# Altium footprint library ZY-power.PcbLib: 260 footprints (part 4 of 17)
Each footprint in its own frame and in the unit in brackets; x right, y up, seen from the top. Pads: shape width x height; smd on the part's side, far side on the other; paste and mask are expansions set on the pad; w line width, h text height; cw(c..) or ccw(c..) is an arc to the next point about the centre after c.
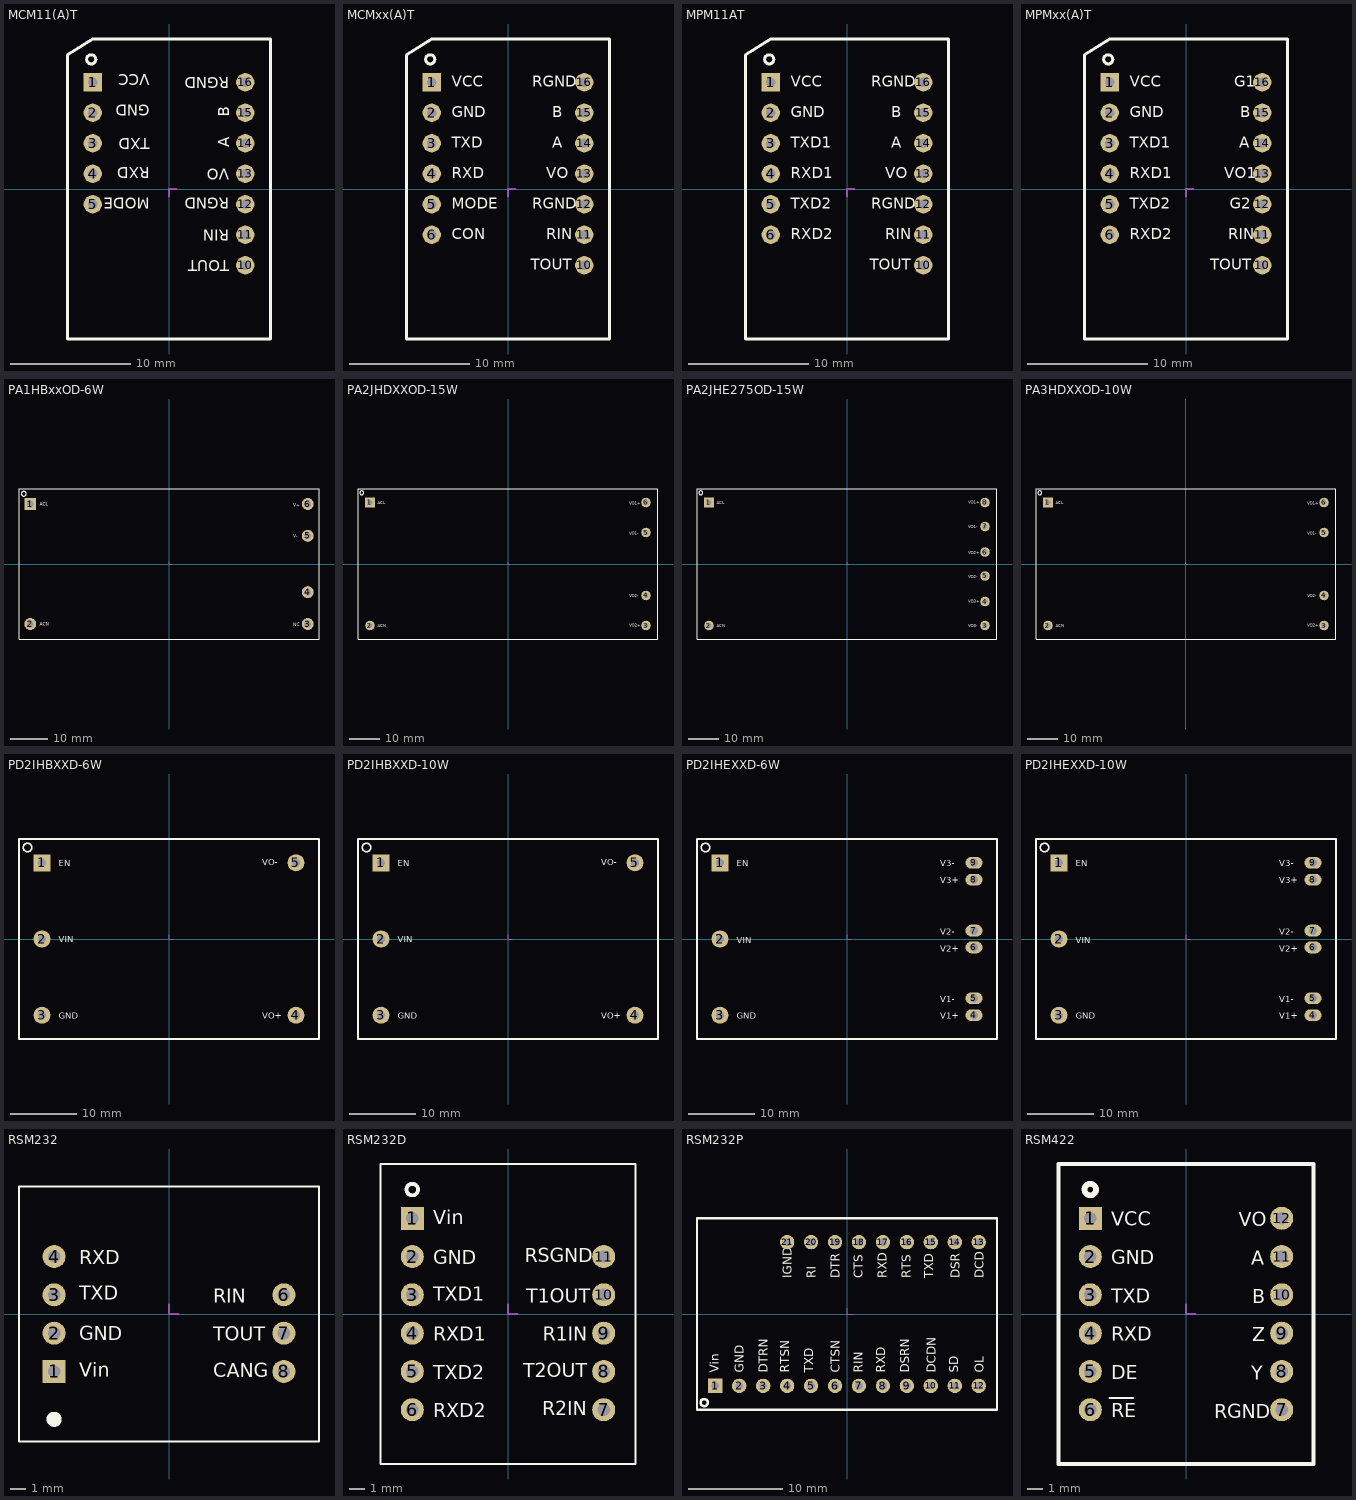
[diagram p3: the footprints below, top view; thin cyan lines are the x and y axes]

## MCM11(A)T [mil]
height 279.53
pads (12):
  rect 60x60 hole 32: 1(-250,350)
  round 60 hole 32: 2(-250,250) 3(-250,150) 4(-250,50) 5(-250,-50) 10(250,-250) 11(250,-150) 12(250,-50) 13(250,50) 14(250,150) 15(250,250) 16(250,350)
Top Overlay:
  circle w10: c-255,425 r15
  lines w10: -249.97,491.68 -332.68,440 -332.68,-491.73 332.68,-491.73 332.68,491.73 -249.97,491.73
  text "RGND" at 197.68,366.73 h36
  text "B" at 197.68,236.73 h36
  text "A" at 197.68,136.73 h36
  text "VO" at 197.68,66.73 h36
  text "RGND" at 197.68,-28.27 h36
  text "RIN" at 197.68,-133.27 h36
  text "TOUT" at 197.68,-233.27 h36
  text "MODE" at -62.32,-28.27 h36
  text "RXD" at -62.32,71.73 h36
  text "TXD" at -62.32,166.73 h36
  text "GND" at -62.32,276.73 h36
  text "VCC" at -62.32,376.73 h36
Mechanical 15:
  lines w5: 0,-25 0,0 25,0

## MCMxx(A)T [mil]
height 279.53
pads (13):
  rect 60x60 hole 32: 1(-250,350)
  round 60 hole 32: 2(-250,250) 3(-250,150) 4(-250,50) 5(-250,-50) 6(-250,-150) 10(250,-250) 11(250,-150) 12(250,-50) 13(250,50) 14(250,150) 15(250,250) 16(250,350)
Top Overlay:
  circle w10: c-255,425 r15
  lines w10: -249.97,491.68 -332.68,440 -332.68,-491.73 332.68,-491.73 332.68,491.73 -249.97,491.73
  text "MODE" at -185,-65 h36
  text "CON" at -185,-165 h36
  text "RGND" at 80,335 h36
  text "B" at 145,235 h36
  text "A" at 145,135 h36
  text "VO" at 125,35 h36
  text "RGND" at 80,-65 h36
  text "RIN" at 125,-165 h36
  text "TOUT" at 75,-265 h36
  text "RXD" at -185,35 h36
  text "TXD" at -185,135 h36
  text "GND" at -185,235 h36
  text "VCC" at -185,335 h36
Mechanical 15:
  lines w5: 0,-25 0,0 25,0

## MPM11AT [mil]
height 279.53
pads (13):
  rect 60x60 hole 32: 1(-250,350)
  round 60 hole 32: 2(-250,250) 3(-250,150) 4(-250,50) 5(-250,-50) 6(-250,-150) 10(250,-250) 11(250,-150) 12(250,-50) 13(250,50) 14(250,150) 15(250,250) 16(250,350)
Top Overlay:
  circle w10: c-255,425 r15
  lines w10: -249.97,491.68 -332.68,440 -332.68,-491.73 332.68,-491.73 332.68,491.73 -249.97,491.73
  text "TXD2" at -185,-65 h36
  text "RXD2" at -185,-165 h36
  text "RGND" at 80,335 h36
  text "B" at 145,235 h36
  text "A" at 145,135 h36
  text "VO" at 125,35 h36
  text "RGND" at 80,-65 h36
  text "RIN" at 125,-165 h36
  text "TOUT" at 75,-265 h36
  text "RXD1" at -185,35 h36
  text "TXD1" at -185,135 h36
  text "GND" at -185,235 h36
  text "VCC" at -185,335 h36
Mechanical 15:
  lines w5: 0,-25 0,0 25,0

## MPMxx(A)T [mil]
height 279.53
pads (13):
  rect 60x60 hole 32: 1(-250,350)
  round 60 hole 32: 2(-250,250) 3(-250,150) 4(-250,50) 5(-250,-50) 6(-250,-150) 10(250,-250) 11(250,-150) 12(250,-50) 13(250,50) 14(250,150) 15(250,250) 16(250,350)
Top Overlay:
  circle w10: c-255,425 r15
  lines w10: -249.97,491.68 -332.68,440 -332.68,-491.73 332.68,-491.73 332.68,491.73 -249.97,491.73
  text "TXD2" at -185,-65 h36
  text "RXD2" at -185,-165 h36
  text "G1" at 158.94,335 h36
  text "B" at 177.45,235 h36
  text "A" at 174.02,135 h36
  text "VO1" at 125,35 h36
  text "G2" at 143.51,-65 h36
  text "RIN" at 137.85,-165 h36
  text "TOUT" at 79.41,-265 h36
  text "RXD1" at -185,35 h36
  text "TXD1" at -185,135 h36
  text "GND" at -185,235 h36
  text "VCC" at -185,335 h36
Mechanical 15:
  lines w5: 0,-25 0,0 25,0

## PA1HBxxOD-6W [mm]
pads (6):
  rect 3.175x3.175 hole 1.778: 1(-37,16)
  round 3.175 hole 1.778: 2(-37,-16) 3(37,-16) 4(37,-7.5) 5(37,7.5) 6(37,16)
Top Overlay:
  circle w0.254: c-38.73,18.73 r0.635
  lines w0.254: -40,-20 -40,20 40,20 40,-20 -40,-20
  text "NC" at 33.19,-16.635 h0.91
  text "V-" at 33.19,6.987 h0.91
  text "V+" at 33.19,15.24 h0.91
  text "ACN" at -34.46,-16.506 h0.91
  text "ACL" at -34.46,15.494 h0.91
Mechanical 15:
  lines w0.127: 0,0.635 0,0 0.635,0

## PA2JHDXXOD-15W [mm]
pads (6):
  rect 3.175x3.175 hole 1.778: 1(-46,20.5)
  round 3.175 hole 1.778: 2(-46,-20.5) 3(46,-20.5) 4(46,-10.5) 5(46,10.5) 6(46,20.5)
Top Overlay:
  circle w0.254: c-48.73,23.73 r0.635
  lines w0.254: -50,-25 50,-25 50,25 -50,25 -50,-25
  text "ACL" at -43.46,19.939 h0.91
  text "ACN" at -43.46,-21.061 h0.91
  text "VO2+" at 40.412,-20.955 h0.91
  text "VO2-" at 40.412,-11.049 h0.91
  text "VO1-" at 40.412,9.779 h0.91
  text "VO1+" at 40.412,19.779 h0.91
Mechanical 15:
  lines w0.127: 0,0.635 0,0 0.635,0

## PA2JHE275OD-15W [mm]
pads (8):
  rect 3.175x3.175 hole 1.778: 1(-46,20.5)
  round 3.175 hole 1.778: 2(-46,-20.5) 3(46,-20.5) 4(46,-12.5) 5(46,-4) 6(46,4) 7(46,12.5) 8(46,20.5)
Top Overlay:
  circle w0.254: c-48.73,23.73 r0.635
  lines w0.254: -50,-25 50,-25 50,25 -50,25 -50,-25
  text "ACL" at -43.46,19.939 h0.91
  text "ACN" at -43.46,-21.061 h0.91
  text "VO3+" at 40.412,-12.954 h0.91
  text "VO3-" at 40.412,-21.082 h0.91
  text "VO1-" at 40.412,11.938 h0.91
  text "VO1+" at 40.412,20.033 h0.91
  text "VO2+" at 40.412,3.302 h0.91
  text "VO2-" at 40.412,-4.699 h0.91
Mechanical 15:
  lines w0.127: 0,0.635 0,0 0.635,0

## PA3HDXXOD-10W [mm]
pads (6):
  rect 3.175x3.175 hole 1.778: 1(-46,20.5)
  round 3.175 hole 1.778: 2(-46,-20.5) 3(46,-20.5) 4(46,-10.5) 5(46,10.5) 6(46,20.5)
Top Overlay:
  circle w0.254: c-48.73,23.73 r0.635
  lines w0.254: -50,-25 -50,25 50,25 50,-25 -50,-25
  text "VO1+" at 40.412,19.779 h0.91
  text "VO1-" at 40.412,9.779 h0.91
  text "VO2-" at 40.412,-11.049 h0.91
  text "VO2+" at 40.412,-20.955 h0.91
  text "ACN" at -43.46,-21.061 h0.91
  text "ACL" at -43.46,19.939 h0.91
Mechanical 15:
  lines w0.127: 0,0.635 0,0 0.635,0

## PD2IHBXXD-6W [mil]
pads (5):
  rect 100x100 hole 50: 1(-750,450)
  round 100 hole 50: 2(-750,0) 3(-750,-450) 4(750,-450) 5(750,450)
Top Overlay:
  circle w10: c-835.83,540.55 r25
  lines w10: -885.83,-590.55 -885.83,590.55 885.83,590.55 885.83,-590.55 -885.83,-590.55
  text "EN" at -650,430.08 h36
  text "VIN" at -650,-19.92 h36
  text "GND" at -650,-469.92 h36
  text "VO+" at 550,-470 h36
  text "VO-" at 550,435 h36
Mechanical 15:
  lines w5: 0,25 0,0 25,0

## PD2IHBXXD-10W [mil]
pads (5):
  rect 100x100 hole 50: 1(-750,450)
  round 100 hole 50: 2(-750,0) 3(-750,-450) 4(750,-450) 5(750,450)
Top Overlay:
  circle w10: c-835.83,540.55 r25
  lines w10: -885.83,-590.55 885.83,-590.55 885.83,590.55 -885.83,590.55 -885.83,-590.55
  text "VO-" at 550,435 h36
  text "VO+" at 550,-470 h36
  text "GND" at -650,-469.92 h36
  text "VIN" at -650,-19.92 h36
  text "EN" at -650,430.08 h36
Mechanical 15:
  lines w5: 0,25 0,0 25,0

## PD2IHEXXD-6W [mil]
pads (9):
  rect 100x100 hole 50 unplated: 1(-750,450)
  round 100 hole 50 unplated: 2(-750,0) 3(-750,-450)
  oval 100x70 hole 50 unplated: 4(750,-450) 5(750,-350) 6(750,-50) 7(750,50) 8(750,350) 9(750,450)
Top Overlay:
  circle w10: c-835.83,540.55 r25
  lines w10: -885.83,-590.55 885.83,-590.55 885.83,590.55 -885.83,590.55 -885.83,-590.55
  text "EN" at -650,430 h36
  text "VIN" at -650,-25 h36
  text "GND" at -650,-470 h36
  text "V1+" at 550,-470 h36
  text "V1-" at 550,-375 h36
  text "V2+" at 550,-75 h36
  text "V2-" at 550,25 h36
  text "V3+" at 550,330 h36
  text "V3-" at 550,430 h36
Mechanical 15:
  lines w5: 0,25 0,0 25,0

## PD2IHEXXD-10W [mil]
pads (9):
  rect 100x100 hole 50 unplated: 1(-750,450)
  round 100 hole 50 unplated: 2(-750,0) 3(-750,-450)
  oval 100x70 hole 50 unplated: 4(750,-450) 5(750,-350) 6(750,-50) 7(750,50) 8(750,350) 9(750,450)
Top Overlay:
  circle w10: c-835.83,540.55 r25
  lines w10: -885.83,-590.55 885.83,-590.55 885.83,590.55 -885.83,590.55 -885.83,-590.55
  text "EN" at -650,430 h36
  text "VIN" at -650,-25 h36
  text "GND" at -650,-470 h36
  text "V1+" at 550,-470 h36
  text "V1-" at 550,-375 h36
  text "V2+" at 550,-75 h36
  text "V2-" at 550,25 h36
  text "V3+" at 550,330 h36
  text "V3-" at 550,430 h36
Mechanical 15:
  lines w5: 0,25 0,0 25,0

## RSM232 [mil]
height 279.53
pads (7):
  rect 60x60 hole 32: 1(-300,-150)
  round 60 hole 32: 2(-300,-50) 3(-300,50) 4(-300,150) 6(300,50) 7(300,-50) 8(300,-150)
Top Overlay:
  circle w19.68: c-300,-275 r9.84
  lines w5: -391.73,-332.68 391.73,-332.68 391.73,332.68 -391.73,332.68 -391.73,-332.68
  text "RIN" at 115,30 h36
  text "TOUT" at 115,-70 h36
  text "Vin" at -235,-164 h36
  text "GND" at -235,-69 h36
  text "TXD" at -235,37 h36
  text "RXD" at -235,130 h36
  text "CANG" at 115,-165 h36
Mechanical 15:
  lines w5: 0,25 0,0 25,0

## RSM232D [mil]
height 279.53
pads (11):
  rect 60x60 hole 32: 1(-250,250)
  round 60 hole 32: 2(-250,150) 3(-250,50) 4(-250,-50) 5(-250,-150) 6(-250,-250) 7(250,-250) 8(250,-150) 9(250,-50) 10(250,50) 11(250,150)
Top Overlay:
  circle w10: c-250,325 r15
  lines w5: -332.68,-391.73 332.68,-391.73 332.68,391.73 -332.68,391.73 -332.68,-391.73
  text "RXD2" at -195,-270 h36
  text "TXD2" at -195,-170 h36
  text "R2IN" at 89.37,-265 h36
  text "T2OUT" at 40.16,-165 h36
  text "R1IN" at 91.34,-70 h36
  text "RXD1" at -195,-70 h36
  text "TXD1" at -195,35 h36
  text "GND" at -195,130 h36
  text "Vin" at -195,235 h36
  text "T1OUT" at 48.03,30 h36
  text "RSGND" at 44.09,135 h36
Mechanical 15:
  lines w5: 0,25 0,0 25,0

## RSM232P [mil]
height 413.39
pads (21):
  rect 60x60 hole 32: 1(-550,-300)
  round 60 hole 32: 2(-450,-300) 3(-350,-300) 4(-250,-300) 5(-150,-300) 6(-50,-300) 7(50,-300) 8(150,-300) 9(250,-300) 10(350,-300) 11(450,-300) 12(550,-300) 13(550,300) 14(450,300) 15(350,300) 16(250,300) 17(150,300) 18(50,300) 19(-50,300) 20(-150,300) 21(-250,300)
Top Overlay:
  circle w10: c-595.98,-369.61 r15
  lines w10: -625.98,-399.61 625.98,-399.61 625.98,399.61 -625.98,399.61 -625.98,-399.61
  text "Vin" at -535,-245 h36
  text "GND" at -430,-245 h36
  text "DTRN" at -330,-245 h36
  text "RTSN" at -240,-245 h36
  text "TXD" at -140,-245 h36
  text "CTSN" at -30,-245 h36
  text "RIN" at 65,-245 h36
  text "RXD" at 160,-245 h36
  text "DSRN" at 260,-245 h36
  text "DCDN" at 370,-245 h36
  text "SD" at 465,-245 h36
  text "OL" at 570,-245 h36
  text "DCD" at 570,150 h36
  text "DSR" at 470,150 h36
  text "TXD" at 360,150 h36
  text "RTS" at 265,150 h36
  text "RXD" at 165,150 h36
  text "CTS" at 65,150 h36
  text "DTR" at -30,150 h36
  text "RI" at -130,150 h36
  text "IGND" at -230,150 h36
Mechanical 15:
  lines w5: 0,25 0,0 25,0

## RSM422 [mil]
height 277.56
pads (12):
  rect 60x60 hole 32: 1(-250,250)
  round 60 hole 32: 2(-250,150) 3(-250,50) 4(-250,-50) 5(-250,-150) 6(-250,-250) 7(250,-250) 8(250,-150) 9(250,-50) 10(250,50) 11(250,150) 12(250,250)
Top Overlay:
  circle w15: c-250,325 r15
  lines w6: -199.8,-219.49 -138.78,-219.49
  lines w10: -332.68,-391.73 -332.68,391.73 332.68,391.73 332.68,-391.73 -332.68,-391.73
  text "DE" at -195,-170 h36
  text "RE" at -195,-270 h36
  text "RGND" at 73.69,-272 h36
  text "Y" at 170.18,-171.8 h36
  text "RXD" at -195,-70 h36
  text "TXD" at -195,30 h36
  text "GND" at -195,130 h36
  text "VCC" at -195,230 h36
  text "A" at 170.18,128.8 h36
  text "B" at 173.61,28.6 h36
  text "Z" at 173.61,-71.6 h36
  text "VO" at 138.13,229 h36
Mechanical 15:
  lines w5: 0,25 0,0 25,0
